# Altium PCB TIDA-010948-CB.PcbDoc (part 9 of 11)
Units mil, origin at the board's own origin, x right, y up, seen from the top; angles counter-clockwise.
Board outline 8100 x 8400 mil, 8 copper layers (L01 - TOP, L02 - GND, L03 - SIG, L04 - GND, L05 - PWR, L06 - SIG, L07 - GND, L08 - BOTTOM), stack 59.656 mil thick; 711 components, 572 nets, 2646 pads, 1325 vias.
Unrouted connection lines stored in the file: 988.
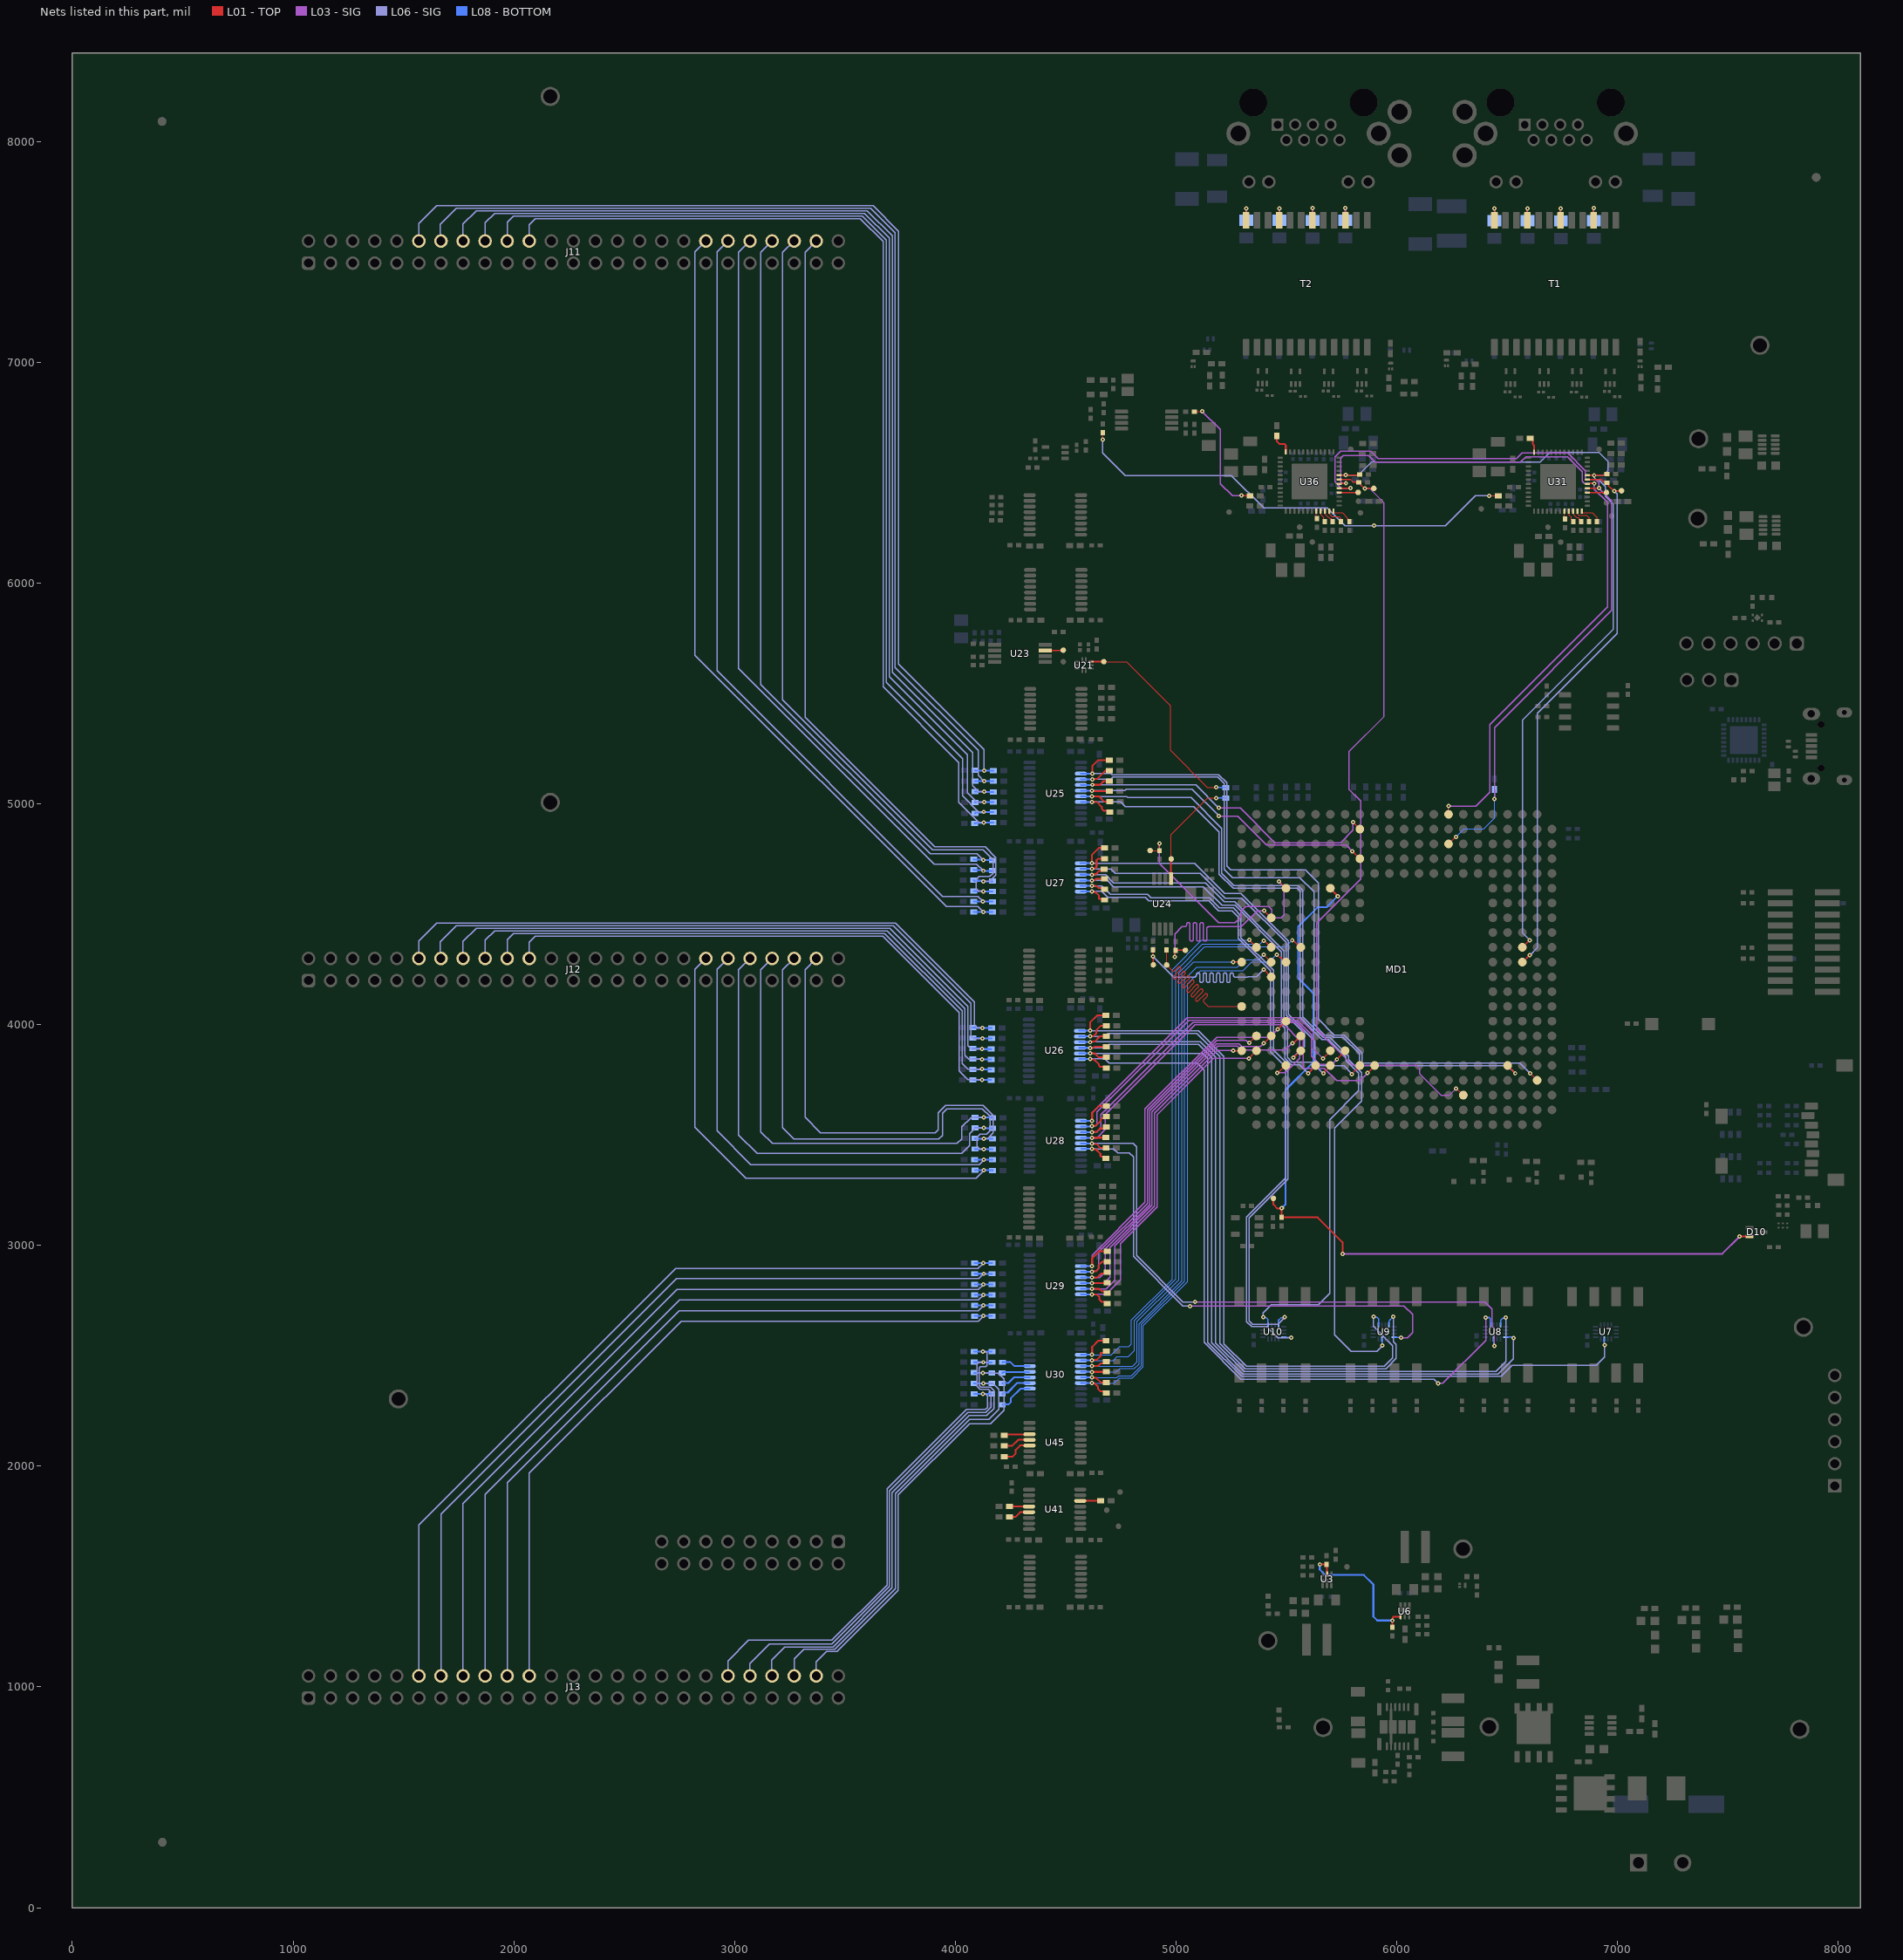
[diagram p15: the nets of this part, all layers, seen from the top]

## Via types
v1: diameter 19.68, hole 7.87, L01 - TOP to L08 - BOTTOM, 1310 vias
v2: diameter 20, hole 7.87, L01 - TOP to L08 - BOTTOM, tented both sides, 7 vias
v3: diameter 200, hole 144, L01 - TOP to L08 - BOTTOM, 6 vias
v4: diameter 20, hole 8, L01 - TOP to L08 - BOTTOM, tented both sides, 2 vias

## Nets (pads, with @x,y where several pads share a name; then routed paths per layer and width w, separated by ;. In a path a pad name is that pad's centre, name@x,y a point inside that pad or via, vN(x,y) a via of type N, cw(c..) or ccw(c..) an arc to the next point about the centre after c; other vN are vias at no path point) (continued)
NetR202_1: R202.1 U30.20 | length 130.9
  L08 - BOTTOM w8: R202.1@4213.62,2470 4214.52,2470.9 4250.02,2470.9 4267.53,2453.39 U30.20@4336.86,2453.39
NetR203_1: R203.1 U30.19 | length 123.6
  L08 - BOTTOM w8: R203.1@4212.68,2422.81 4214.8,2422.81 4217.92,2425.94 U30.19@4335,2425.94
NetR204_1: R204.1 U30.18 | length 134.9
  L08 - BOTTOM w8: R204.1@4213.62,2374 4216.22,2376.59 4240.98,2376.59 4266.59,2402.2 U30.18@4336.86,2402.2
NetR205_1: R205.1 U30.17 | length 144.4
  L08 - BOTTOM w8: R205.1@4213.62,2325.5 4221.43,2333.31 4237.4,2333.31 4280.7,2376.61 U30.17@4336.86,2376.61
NetR206_1: R206.1 U30.16 | length 162.9
  L08 - BOTTOM w8: R206.1@4214.12,2278 4215.62,2279.5 4241,2279.5 4250.5,2289 4250.5,2305.91 4295.61,2351.02 U30.16@4336.86,2351.02
NetR229_1: R229.1 T1.24 | length 110.4
  L01 - TOP w6: T1.24@6442,7642.5 6442.5,7643 v1(6442.5,7697)
  L08 - BOTTOM w6: v1(6442.5,7697) 6442.5,7642 R229.1@6443,7641.5
NetR230_2: R230.2 U31.32 | length 35.6
  L01 - TOP w4.25: U31.32@6759.53,6325.14 6759.53,6293.54 R230.2@6762.36,6290.71
NetR231_1: R231.1 T1.21 | length 109.7
  L01 - TOP w6: T1.21@6592,7642.5 v1(6592,7696.5)
  L08 - BOTTOM w6: v1(6592,7696.5) 6592,7641.5 R231.1@6592.5,7641
NetR233_2: R233.2 U31.33 | length 54.9
  L01 - TOP w4.25: U31.33@6779.21,6325.14 6781.81,6322.54 6781.81,6307.57 6791.26,6298.12 6791.26,6286.15 R233.2@6798.98,6278.43
NetR234_2: R234.2 U31.34 | length 66.6
  L01 - TOP w4.25: U31.34@6798.9,6325.14 6801.5,6322.54 6801.5,6309.89 6814.43,6296.96 6822.41,6296.96 6827.28,6292.08 6827.28,6285.9 R234.2@6835,6278.19
NetR235_1: R235.1 U31.12 | length 71.9
  L01 - TOP w8: R235.1@6603.62,6655 6607.56,6655 6615.37,6647.19 6615.37,6630.02 6621.73,6623.65 U31.12@6621.73,6592.86
NetR237_2: R237.2 U31.35 | length 88.1
  L01 - TOP w4.25: U31.35@6818.58,6325.14 6821.18,6322.54 6821.18,6310.2 6825.18,6306.21 6859.23,6306.21 6871,6294.43 R237.2@6871,6278.69
NetR238_2: R238.2 U31.36 | length 101.4
  L01 - TOP w4.25: U31.36@6838.27,6325.14 6838.27,6320.85 6840.87,6318.25 6868.13,6318.25 6886.28,6318.25 6906.72,6297.81 R238.2@6906.72,6278.69
NetR245_1: R245.1 T1.18 | length 111.6
  L01 - TOP w6: T1.18@6742,7642.5 v1(6742,7697)
  L08 - BOTTOM w6: v1(6742,7697) 6742,7642 R245.1@6743.5,7640.5
NetR248_1: R248.1 T1.15 | length 112.7
  L01 - TOP w6: T1.15@6892,7642.5 v1(6892,7698)
  L08 - BOTTOM w6: v1(6892,7698) 6892,7641.5 R248.1@6892.5,7641
NetR269_1: R269.1 T2.24 | length 108.9
  L01 - TOP w4.5: T2.24@5317,7642.5 T2.24@5318,7643.5
  L01 - TOP w6: T2.24@5318,7643.5 v1(5318,7697)
  L08 - BOTTOM w6: R269.1@5318,7643 v1(5318,7697)
NetR270_2: R270.2 U36.32 | length 35.6
  L01 - TOP w4.25: U36.32@5634.67,6325.61 5634.67,6294.02 R270.2@5637.5,6291.19
NetR271_1: R271.1 T2.21 | length 108.9
  L01 - TOP w6: T2.21@5467,7642.5 5468,7643.5 v1(5468,7697)
  L08 - BOTTOM w6: R271.1@5468,7643 v1(5468,7697)
NetR273_2: R273.2 U36.33 | length 55.7
  L01 - TOP w4.25: U36.33@5654.35,6325.61 5656.95,6323.01 5656.95,6308.05 5668,6297 5668,6282.69 R273.2@5673,6277.69
NetR274_2: R274.2 U36.34 | length 65.7
  L01 - TOP w4.25: U36.34@5674.04,6325.61 5676.64,6323.01 5676.64,6310.36 5688,6299 5690.5,6299 5695.87,6293.63 5699.52,6293.63 5701.78,6291.37 5701.78,6285.9 R274.2@5709.5,6278.19
NetR275_1: R275.1 U36.12 | length 103.2
  L01 - TOP w8: R275.1@5457,6666.38 5457,6640.79 5467.79,6630 5491,6630 5496.87,6624.13 U36.12@5496.87,6593.33
NetR277_2: R277.2 U36.35 | length 88.9
  L01 - TOP w4.25: U36.35@5693.72,6325.61 5696.32,6323.01 5696.32,6310.68 5705.53,6301.47 5738.97,6301.47 5746.5,6293.93 R277.2@5746.5,6278.19
NetR278_2: R278.2 U36.36 | length 99.2
  L01 - TOP w4.25: U36.36@5713.41,6325.61 5713.41,6321.32 5716.01,6318.72 5743.28,6318.72 5753.21,6318.72 5778.22,6293.71 5778.22,6285.05 R278.2@5785.31,6277.96
NetR285_1: R285.1 T2.18 | length 112.3
  L01 - TOP w4.5: T2.18@5617,7642.5 T2.18@5618,7643.5
  L01 - TOP w6: T2.18@5618,7643.5 v1(5618,7698)
  L08 - BOTTOM w8: v1(5618,7698) 5618,7643 R285.1@5619,7642
NetR287_1: R287.1 T2.15 | length 110.9
  L01 - TOP w6: T2.15@5767,7642.5 v1(5767,7698)
  L08 - BOTTOM w8: R287.1@5766,7643 5767,7644 v1(5767,7698)
NetR293_1: R293.1 U41.13 | length 96.7
  L01 - TOP w8: R293.1@4246.12,1770 4271.71,1770 4293.41,1791.7 U41.13@4333.86,1791.7
NetR294_1: R294.1 U41.12 | length 88
  L01 - TOP w8: R294.1@4246.12,1818 4246.48,1817.65 4333.5,1817.65 U41.12@4333.86,1817.29
NetR295_2: R295.2 U41.6 | length 92
  L01 - TOP w8: U41.6@4566.14,1842.88 4566.45,1843.19 4657.57,1843.19 R295.2@4657.88,1843.5
NetR301_1: R301.1 U45.13 | length 145.8
  L01 - TOP w8: R301.1@4221.62,2043.5 4222.62,2042.5 4259,2042.5 4273.5,2057 4273.5,2074 4293.2,2093.7 U45.13@4335.86,2093.7
NetR302_1: R302.1 U45.12 | length 125.7
  L01 - TOP w8: R302.1@4221.62,2091.5 4257,2091.5 4284.8,2119.3 U45.12@4335.86,2119.3
NetR303_1: R303.1 U45.11 | length 116.2
  L01 - TOP w8: R303.1@4222.12,2139 4226.15,2143.03 4334,2143.03 U45.11@4335.86,2144.89
NetTP14_1: TP14.1 U31.40 | length 86.3
  L01 - TOP w5: U31.40@6863.99,6409.66 U31.40@6863.86,6409.79 6863.98,6409.91 TP14.1@6949.74,6409.91 TP14.1@6949.86,6410.03
NetTP19_1: TP19.1 U36.40 | length 86.3
  L01 - TOP w5: U36.40@5739.13,6410.13 U36.40@5739,6410.26 5739.12,6410.38 5824.88,6410.38 TP19.1@5825,6410.5
NetTP24_1: TP24.1 U23.3 | length 82.5
  L01 - TOP w6: U23.3@4407.17,5694.3 4407.93,5695.05 4488.25,5695.05 TP24.1@4489,5695.8
PGOOD_3V3: R13.1 R26.2 U3.2 U6.1 | length 691.2
  L01 - TOP w8: v1(5651,1555) 5651.34,1554.66 5681.66,1554.66 R13.1@5682,1554.32 5683.08,1553.24 5683.08,1512.51 U3.2@5684,1511.59 ; R26.2@5979,1269.69 5979.5,1270.19 5979.5,1300.5 v1(5980,1301) 5981,1302 5981,1313.72 5985.69,1318.41 U6.1@6017.31,1318.41
  L08 - BOTTOM w8: v1(5651,1555) 5651,1532 5676,1507 5851,1507 5894,1464 5894,1318 5911,1301 v1(5980,1301)
PHY1_CLK_IN: R107.2 R246.1 | length 2077.2
  L01 - TOP w4.25: v1(4667.5,6650) R107.2@4667.5,6680.81 ; v1(6419,6395) 6459.88,6395 R246.1@6460.38,6394.5
  L06 - SIG w5.25: v1(4667.5,6650) 4667.5,6589.55 4769.55,6487.5 5249.5,6487.5 5397.24,6339.76 5685.01,6339.76 5764.76,6260 v1(5896.5,6260) 6220,6260 6355.53,6395.53 6418.47,6395.53 v1(6419,6395)
PHY1_RESET: MD1.L20 R243.2 TP32.1 U31.43 | length 2498.7
  L01 - TOP w6: MD1.L20@6568.9,4283.06 6570.48,4283.06 6601.42,4314 v1(6603,4314) ; U31.43@6863.86,6468.84 6926.22,6468.84 6936.07,6459 6945.63,6459 R243.2@6951.5,6453.13 6958.33,6446.3 6958.33,6440.16 6969.2,6429.29 6972.07,6429.29 6984.75,6416.61 v1(6986.03,6416.61) 6986.03,6417.85 TP32.1@7017.88,6417.85
  L06 - SIG w6: v1(6603,4314) 6637,4348 6637,5410 6998.11,5771.11 6998.11,6403.28 6986.03,6415.36 v1(6986.03,6416.61)
PHY2_CLK_IN: R108.2 R286.1 | length 554.5
  L01 - TOP w4.25: R108.2@5083.19,6776 5084.69,6777.5 v1(5118.5,6777.5)
  L01 - TOP w6: v1(5295.5,6396) 5333.38,6396 R286.1@5334.88,6394.5
  L03 - SIG w5.25: v1(5118.5,6777.5) 5201,6695 5201,6450 5255,6396 v1(5295.5,6396)
PHY2_RESET: MD1.Y16 R283.2 TP36.1 U36.43 | length 3673.3
  L01 - TOP w6: U36.43@5739,6469.31 5790.19,6469.31 5802,6457.5 5826.34,6457.5 R283.2@5828.65,6455.19 5829.16,6455.19 5836,6448.35 5836,6445.35 5853.35,6428 v1(5855,6428) 5855.43,6428.43 5895.57,6428.43 TP36.1@5896,6428.86 ; v1(6268.5,3710) 6270.19,3710 6299.49,3680.7 MD1.Y16@6301.18,3680.7
  L03 - SIG w6: v1(5855,6428) 5855.66,6428.66 5876.84,6428.66 5942.05,6363.45 5942.05,5395.55 5782.85,5236.35 5782.85,5066.58 5836.5,5012.93 5836.5,4659 5637.01,4459.51 5637.01,3977.82 5799.88,3814.95 6089.79,3814.95 6103.83,3800.91 6103.83,3776.67 6200.54,3679.96 6238.46,3679.96 v1(6268.5,3710)
PHY_INT: MD1.K20 R242.2 R282.2 U31.44 U36.44 | length 3924.7
  L01 - TOP w6: U36.44@5739,6489 U36.44@5739,6489 5768.94,6488.96 v1(5768.98,6488.93) 5827.89,6488.93 R282.2@5831.09,6492.12 ; MD1.K20@6568.9,4349.99 6569.45,4349.99 6601.95,4382.5 v1(6602.5,4382.5) ; U31.44@6863.86,6488.53 v1(6893.55,6488.53) 6946.3,6488.53 R242.2@6951.97,6494.19
  L06 - SIG w6: v1(5768.98,6488.93) 5826.08,6488.93 5884.66,6547.5 6649.37,6547.5 6692.82,6590.95 6916.18,6590.95 6957.5,6549.63 6957.5,6510 6936.03,6488.53 v1(6893.55,6488.53) 6893.5,6488.47 6893.5,6477.5 6902.16,6468.84 6913.24,6468.84 6945.07,6437.02 6945.07,6393.21 6980.82,6357.45 6980.82,5790.32 6568.81,5378.31 6568.81,4416.19 v1(6602.5,4382.5)
PHY_MDC: MD1.A15 U31.42 U36.42 | length 3342.8
  L01 - TOP w4.25: MD1.A15@6234.25,4952.36 6234.38,4952.48 6234.38,4989.38 v1(6234.5,4989.5)
  L01 - TOP w5: U36.42@5739,6449.63 5739.92,6450.55 5768.58,6450.55 v1(5769.5,6451.47) ; U31.42@6863.86,6449.16 6864.78,6450.08 6893.44,6450.08 v1(6894.36,6451)
  L03 - SIG w5.25: v1(5769.5,6451.47) 5753.33,6451.47 5745.89,6458.91 5745.89,6565.37 5757.2,6576.69 5871.81,6576.69 5901,6547.5 6560.5,6547.5 6584.99,6571.99 6773.37,6571.99 6840.22,6505.14 6840.22,6460.49 6849.71,6451 v1(6894.36,6451) 6894.36,6426.11 6955.25,6365.22 6955.25,5892.75 6421.5,5359 6421.5,5052 6359,4989.5 v1(6234.5,4989.5)
PHY_MDIO: MD1.C15 R236.1 U31.41 U36.41 | length 3666.4
  L01 - TOP w4.25: MD1.C15@6234.25,4818.5 6235.62,4818.5 6267.13,4850 v1(6268.5,4850)
  L01 - TOP w5: U36.41@5739.03,6429.97 v1(5790.5,6430) ; U31.41@6863.86,6429.47 6915.29,6429.5 v1(6915.48,6429.69)
  L03 - SIG w5.25: v1(5790.5,6430) 5748.25,6430 5720.17,6458.07 5720.17,6571.17 5745.89,6596.89 5882.96,6596.89 5916,6563.85 6542.35,6563.85 6567,6588.5 6774.26,6588.5 6854.65,6508.11 6854.65,6473.57 6859.75,6468.47 6901.59,6468.47 6915.48,6454.58 v1(6915.48,6429.69) 6915.48,6429.44 6973.29,6371.64 6973.29,5876.29 6442.5,5345.5 v1(6442.5,5022.5)
  L08 - BOTTOM w4.25: v1(6268.5,4850) 6304.87,4886.37 6393.97,4886.37 6442.5,4934.9 v1(6442.5,5022.5)
  L08 - BOTTOM w5.25: R236.1@6442,5064.88 6442.5,5064.38 v1(6442.5,5022.5)
PORz_OUT: D10.2 MD1.F7 R59.1 TP20.1 | length 4017.1
  L01 - TOP w8: TP20.1@5441,3213 5441,3185 5460,3166 5477,3166 v2(5479,3168) R59.1@5479,3126.69 5641.31,3126.69 5754,3014 v1(5754,2962) ; MD1.F7@5698.82,4617.71 5698.82,4616.45 5732,4583.26 v2(5732,4582) ; v1(7552.5,3040) 7553.16,3040.66 7597.85,3040.66 D10.2@7598.5,3041.31
  L03 - SIG w8: v1(5754,2962) 7474.5,2962 v1(7552.5,3040)
  L08 - BOTTOM w8: v2(5479,3168) 5496,3185 5496,3704.21 5623.01,3831.22 5623.01,4140.67 5553.2,4210.49 5553.2,4444.07 5640.63,4531.5 5681.5,4531.5 v2(5732,4582)
PRG0_IEP1_SYNC0: R128.1 TP30.1 U21.5 | length 965.2
  L01 - TOP w4.25: TP30.1@4672.78,5643.88 4775.62,5643.88 4975,5444.5 4975,5241.5 5142,5074.5 v1(5182.5,5074.5)
  L01 - TOP w8: U21.5@4614.14,5643.88 TP30.1@4672.78,5643.88
  L08 - BOTTOM w6: v1(5182.5,5074.5) 5223.88,5074.5 R128.1@5224.38,5074
PRG0_IEP1_SYNC1: R127.1 TP28.1 U24.1 | length 515.3
  L01 - TOP w4.25: TP28.1@4976.39,4748.62 TP28.1@4978,4750.24 4978,4860 5144,5026 v1(5182.5,5026)
  L01 - TOP w8: U24.1@4976.39,4661.17 TP28.1@4976.39,4748.62
  L08 - BOTTOM w6: v1(5182.5,5026) 5224.38,5026 R127.1@5224.88,5025.5
PRU0_SD0_CLK_SHIFT: MD1.F4 R118.2 TP25.1 | length 1138.3
  L01 - TOP w4.25: TP25.1@4882.5,4788.5 4923.69,4788.5 R118.2@4924.5,4787.69 v1(4924.5,4820.5)
  L01 - TOP w6: v1(5465.5,4647.99) 5466.62,4647.99 5496.91,4617.71 MD1.F4@5498.03,4617.71
  L03 - SIG w5.25: v1(4924.5,4820.5) 4924.5,4729.5 5193,4461 5268.34,4461 5293.78,4486.43 5293.78,4513.54 5314.78,4534.55 5419.96,4534.55 5433,4521.51 5433,4494 5444,4483 5476.23,4483 5489.3,4496.07 5489.3,4624.19 v1(5465.5,4647.99)
PRU0_SD3_CLK_SHIFT: MD1.H3 R119.2 TP26.1 | length 1138
  L01 - TOP w5.25: v1(4995.07,4306.13) 4995.07,4335.19 4997.7,4337.81 5040.69,4337.81 TP26.1@5042,4336.5
  L01 - TOP w6: v1(5399.5,4515.41) MD1.H3@5431.1,4483.85
  L03 - SIG w5.25: v1(4995.07,4306.13) 4995.07,4411.07 5027,4443 5037.24,4443 5039.87,4443 ccw(c5039.87,4450.62) 5047.49,4450.62 5047.49,4454.97 cw(c5055.12,4454.97) 5062.74,4454.97 5062.74,4385.39 ccw(c5070.37,4385.39) 5077.99,4385.39 5077.99,4454.97 cw(c5085.62,4454.97) 5093.24,4454.97 5093.24,4385.39 ccw(c5100.87,4385.39) 5108.49,4385.39 5108.49,4454.97 cw(c5116.12,4454.97) 5123.74,4454.97 5123.74,4385.39 ccw(c5131.37,4385.39) 5138.99,4385.39 5138.99,4435.38 cw(c5146.62,4435.38) 5146.62,4443 5162.5,4443 5295.09,4443 5367.5,4515.41 v1(5399.5,4515.41)
PRU1_SD0_CLK_SHIFT: MD1.M3 R120.2 TP27.1 | length 1061.9
  L01 - TOP w4.25: v1(4896,4308.5) R120.2@4896,4337.81
  L01 - TOP w6: R120.2@4895,4338.81 R120.2@4896,4337.81 ; v1(4896,4308.5) 4896.5,4308 4896.5,4271 TP27.1@4897,4270.5 ; v1(5398,4249.5) 5398,4249.37 5431.1,4216.27 MD1.M3@5431.1,4216.14
  L06 - SIG w5.25: v1(4896,4308.5) 4989.5,4215 5082,4215 5084.63,4215 ccw(c5084.63,4222.62) 5092.25,4222.62 5092.25,4226.21 cw(c5099.88,4226.21) 5107.5,4226.21 5107.5,4198.31 ccw(c5115.13,4198.31) 5122.75,4198.31 5122.75,4226.21 cw(c5130.38,4226.21) 5138,4226.21 5138,4198.31 ccw(c5145.63,4198.31) 5153.25,4198.31 5153.25,4226.21 cw(c5160.88,4226.21) 5168.5,4226.21 5168.5,4198.31 ccw(c5176.13,4198.31) 5183.75,4198.31 5183.75,4226.21 cw(c5191.38,4226.21) 5199,4226.21 5199,4198.31 ccw(c5206.63,4198.31) 5214.25,4198.31 5214.25,4226.21 cw(c5221.88,4226.21) 5229.5,4226.21 5229.5,4198.31 ccw(c5237.13,4198.31) 5244.75,4198.31 5244.75,4226.21 cw(c5252.38,4226.21) 5260,4226.21 5260,4222.62 ccw(c5267.63,4222.62) 5267.63,4215 5284.86,4215 5324.18,4215 5326.12,4216.94 5365.44,4216.94 v1(5398,4249.5)
PRU1_SD3_CLK_SHIFT: MD1.P1 R121.2 TP29.1 | length 1159.5
  L01 - TOP w4.25: R121.2@4957.5,4337.81 TP29.1@4957.5,4270 4982.36,4245.14 4983.87,4243.63 ccw(c4988.91,4248.67) 4993.94,4243.63 5009.72,4259.41 cw(c5014.76,4254.37) 5019.79,4259.41 cw(c5014.76,4254.37) 5019.79,4249.33 4989.4,4218.94 ccw(c4994.44,4213.9) 4989.4,4208.86 ccw(c4994.44,4213.9) 4999.48,4208.86 5029.87,4239.25 cw(c5034.91,4234.22) 5039.95,4239.25 cw(c5034.91,4234.22) 5039.95,4229.18 5009.56,4198.79 ccw(c5014.6,4193.75) 5009.56,4188.71 ccw(c5014.6,4193.75) 5019.63,4188.71 5050.02,4219.1 cw(c5055.06,4214.06) 5060.1,4219.1 cw(c5055.06,4214.06) 5060.1,4209.02 5029.71,4178.64 ccw(c5034.75,4173.6) 5029.71,4168.56 ccw(c5034.75,4173.6) 5039.79,4168.56 5070.18,4198.95 cw(c5075.21,4193.91) 5080.25,4198.95 cw(c5075.21,4193.91) 5080.25,4188.87 5049.86,4158.48 ccw(c5054.9,4153.44) 5049.86,4148.41 ccw(c5054.9,4153.44) 5059.94,4148.41 5090.33,4178.8 cw(c5095.37,4173.76) 5100.4,4178.8 cw(c5095.37,4173.76) 5100.4,4168.72 5070.02,4138.33 ccw(c5075.05,4133.29) 5070.01,4128.25 ccw(c5075.05,4133.29) 5080.09,4128.25 5110.48,4158.64 cw(c5115.52,4153.61) 5120.56,4158.64 cw(c5115.52,4153.61) 5120.56,4148.57 5090.17,4118.18 ccw(c5095.21,4113.14) 5090.17,4108.1 ccw(c5095.21,4113.14) 5100.24,4108.1 5130.63,4138.49 cw(c5135.67,4133.45) 5140.71,4138.49 cw(c5135.67,4133.45) 5140.71,4128.41 5124.94,4112.64 ccw(c5129.97,4107.6) 5124.94,4102.56 5139.26,4088.24 5145.22,4082.28 MD1.P1@5297.24,4082.28
PWM_A1_H: MD1.W21 R145.1 U25.3 | length 3373.5
  L01 - TOP w6: v1@6604,3779.73 MD1.W21@6635.83,3747.9
  L01 - TOP w8: v1(4620,5137) 4620,5171.29 4646.02,5197.31 R145.1@4698.25,5197.31 ; v1@6604,3779.73 v1(6604,3780) ; MD1.W21@6635.83,3747.63 MD1.W21@6635.83,3747.9
  L06 - SIG w5.25: v1(4620,5137) 4705.34,5137 4710.3,5132.03 5193,5132.03 5229.38,5095.65 5229.38,4718.12 5247.1,4700.4 5584.82,4700.4 5644.2,4641.02 5644.2,4024.29 5715.6,3952.89 5761.28,3952.89 5843.17,3870.99 5843.17,3828.18 5846.04,3825.31 6558.69,3825.31 v1(6604,3780)
  L08 - BOTTOM w8: U25.3@4569.14,5136.57 4569.36,5136.78 4619.78,5136.78 v1(4620,5137)
PWM_A1_L: MD1.V19 R146.1 U25.4 | length 3274.7
  L01 - TOP w6: MD1.V19@6501.97,3814.05 v1@6536,3780.01
  L01 - TOP w8: v1(4620,5111.5) 4620.84,5112.34 4641.84,5112.34 4679.31,5149.81 R146.1@4697.75,5149.81 ; MD1.V19@6501.97,3814.05 MD1.V19@6501.97,3814.56 ; v1(6536,3779.5) v1@6536,3780.01
  L06 - SIG w5.25: v1(4620,5111.5) 4704.97,5111.5 4715.25,5121.78 5188.72,5121.78 5218.5,5092 5218.5,4702.5 5255.54,4665.46 5560.34,4665.46 5624.42,4601.37 5624.42,4001.07 5672.43,3953.07 5700.92,3953.07 5711.35,3942.64 5756.5,3942.64 5830.77,3868.37 5830.77,3826.08 5842.64,3814.21 6501.29,3814.21 v1(6536,3779.5)
  L08 - BOTTOM w8: U25.4@4569.14,5110.98 4569.4,5111.24 4619.74,5111.24 v1(4620,5111.5)
PWM_A2_H: MD1.V9 R173.1 U27.3 | length 2033.9
  L01 - TOP w6: v1(5795.65,3776.15) 5795.65,3776.84 5832.68,3813.87 MD1.V9@5832.68,3814.56
  L01 - TOP w8: v1(4618.56,4730.94) 4618.56,4768.77 4649.79,4800 R173.1@4675.38,4800
  L06 - SIG w5.25: v1(4618.56,4730.94) 5083.56,4730.94 5220.36,4594.14 5293.01,4594.14 5508.72,4378.43 5508.72,4046.77 5630.08,3925.4 5630.08,3834.16 5650.62,3813.63 5760.87,3813.63 5795.65,3778.85 v1(5795.65,3776.15)
  L08 - BOTTOM w8: U27.3@4567.96,4730.68 4618.3,4730.68 v1(4618.56,4730.94)
PWM_A2_L: MD1.U5 R174.1 U27.4 | length 1785.7
  L01 - TOP w6: v1(5531,3851) 5532.74,3851 5563.23,3881.49 MD1.U5@5564.96,3881.49
  L01 - TOP w8: v1(4618.56,4705.44) 4620.79,4707.68 4633.18,4707.68 4639.5,4714 4639.5,4744.5 4647,4752 R174.1@4675.38,4752
  L06 - SIG w5.25: v1(4618.56,4705.44) 4704.51,4705.44 4724.95,4685 5110.5,4685 5222.5,4573 5298.34,4573 5498.47,4372.87 5498.47,4042.52 5581,3959.99 5581,3901 v1(5531,3851)
  L08 - BOTTOM w8: U27.4@4568.01,4705.14 4618.25,4705.14 v1(4618.56,4705.44)
PWM_A3_H: R151.1 U9.1 U26.3 | length 3229.4
  L01 - TOP w8: v1(4611.56,3972.44) 4611.56,4010.56 4643,4042 R151.1@4682.88,4042
  L06 - SIG w5.25: v1(4611.56,3972.44) 4613,3971 5101.46,3971 5216.29,3856.18 5216.29,2554.27 5318.56,2452 5942.57,2452 5981,2490.43 5981,2546.5 5894,2633.5 v1(5894,2676)
  L08 - BOTTOM w6: v1(5894,2676) 5896.62,2673.38 5911.32,2673.38 5912.97,2671.73 5913.14,2671.73 5917.38,2667.49 U9.1@5917.38,2637.53
  L08 - BOTTOM w8: U26.3@4560.96,3972.18 4611.3,3972.18 v1(4611.56,3972.44)
PWM_A3_L: R152.1 U9.4 U26.4 | length 3193
  L01 - TOP w8: v1(4611.23,3947.27) 4611.56,3946.94 4612,3946.5 4624.47,3946.5 4638.97,3961 4638.97,3975.19 4657.79,3994 R152.1@4683.38,3994
  L06 - SIG w5.25: v1(4611.23,3947.27) 4611.5,3947 4677.79,3947 4690.79,3960 5093.45,3960 5198.75,3854.7 5198.75,2556.25 5314,2441 5951,2441 5997.5,2487.5 5997.5,2551.5 5984.69,2564.32 v1(5984.69,2677)
  L08 - BOTTOM w6: U9.4@5964.62,2639.5 5964.62,2657.62 5970,2663 5970,2663.3 5983.7,2677 v1(5984.69,2677)
  L08 - BOTTOM w8: U26.4@4561.02,3946.62 4610.59,3946.62 v1(4611.23,3947.27)
PWM_A4_H: MD1.U7 R179.1 U28.3 | length 1593.3
  L01 - TOP w6: v1(5665.5,3846) 5665.5,3847.09 5698.82,3880.4 MD1.U7@5698.82,3881.49
  L01 - TOP w8: v1(4619.74,3564.83) 4619.74,3600.93 4649.19,3630.38 R179.1@4683.38,3630.38
  L03 - SIG w5.25: v1(4619.74,3564.83) 4619.74,3600.93 5050.31,4031.5 5555.66,4031.5
  L03 - SIG w6: 5555.66,4031.5 5623.73,3963.43 5623.73,3887.77 v1(5665.5,3846)
  L08 - BOTTOM w8: U28.3@4569.14,3564.57 4619.48,3564.57 v1(4619.74,3564.83)
PWM_A4_L: MD1.U8 R180.1 U28.4 | length 1681.1
  L01 - TOP w6: v1(5728.04,3841.54) 5728.04,3842.66 5765.75,3880.37 MD1.U8@5765.75,3881.49
  L01 - TOP w8: v1(4619.74,3539.33) 4621.91,3541.5 4635,3541.5 4658.75,3565.25 4658.75,3570.46 4663.43,3575.14 4675.31,3575.14 R180.1@4683.13,3582.96
  L03 - SIG w5.25: v1(4619.74,3539.33) 4622.19,3541.79 4635.29,3541.79 4641.5,3548 4641.5,3604 5057.6,4020.1 5547.89,4020.1 5613.11,3954.88 5613.11,3856.9 5651.09,3818.92 5705.42,3818.92 v1(5728.04,3841.54)
  L08 - BOTTOM w8: U28.4@4569.19,3539.02 4619.43,3539.02 v1(4619.74,3539.33)
PWM_A5_H: MD1.R4 R193.1 U29.3 | length 1782.2
  L01 - TOP w6: v1(5461,3979.5) 5461.59,3979.5 5497.44,4015.35 MD1.R4@5498.03,4015.35
  L01 - TOP w8: v1(4619.74,2906.33) 4619.74,2941.74 4651,2973 R193.1@4688.38,2973
  L03 - SIG w5.25: v1(4619.74,2906.33) 4619.27,2906.8 4619.27,2954.26 4859.5,3194.5 4859.5,3618.09 5183.93,3942.52 5424.02,3942.52 v1(5461,3979.5)
  L08 - BOTTOM w8: U29.3@4569.14,2906.07 4619.48,2906.07 v1(4619.74,2906.33)
PWM_A5_L: MD1.T2 R194.1 U29.4 | length 1635.1
  L01 - TOP w6: v1(5331,3917.5) 5332.13,3917.5 5363.05,3948.42 MD1.T2@5364.17,3948.42
  L01 - TOP w8: v1(4619.74,2880.83) 4621.41,2882.5 4637,2882.5 4649,2894.5 4649,2910.29 4664.21,2925.5 R194.1@4688.38,2925.5
  L03 - SIG w5.25: v1(4619.74,2880.83) 4621.87,2882.96 4637.46,2882.96 4649,2894.5 4649,2969.5 4869.75,3190.25 4869.75,3613.84 5184.65,3928.74 5317.18,3928.74 5328.42,3917.5 v1(5331,3917.5)
  L08 - BOTTOM w8: U29.4@4569.19,2880.52 4619.43,2880.52 v1(4619.74,2880.83)
PWM_A6_H: MD1.K2 R207.1 U30.3 | length 2582
  L01 - TOP w6: v1(5331.5,4383) 5331.5,4382.83 5364.17,4350.16 MD1.K2@5364.17,4349.99
  L01 - TOP w8: v1(4619.74,2504.84) 4619.74,2539.76 4648.12,2568.14 R207.1@4682.98,2568.14
  L03 - SIG w5.25: v1@5330.5,4382 v1(5331.5,4383)
  L08 - BOTTOM w4.25: v1(4619.74,2504.84) 4707.18,2504.84 4743.77,2541.43 4785.93,2541.43 4798,2553.5 4798,2662 4982.36,2846.36 4982.36,4248.86 5115.5,4382 v1@5330.5,4382
  L08 - BOTTOM w8: U30.3@4569.14,2504.57 4619.48,2504.58 v1(4619.74,2504.84)
PWM_A6_L: MD1.K3 R208.1 U30.4 | length 2648.9
  L01 - TOP w6: v1(5397,4380.5) 5398.8,4380.5 5429.3,4349.99 MD1.K3@5431.1,4349.99
  L01 - TOP w8: v1(4619.74,2479.34) 4621.97,2481.58 4641.58,2481.58 4658.06,2498.06 4658.06,2510.99 4660.19,2513.12 4675.84,2513.12 R208.1@4683.65,2520.93
  L08 - BOTTOM w4.25: v1(4619.74,2479.34) 4716.1,2479.34 4732.26,2495.5 4784.5,2495.5 4812,2523 4812,2660.5 4998.44,2846.94 4998.44,4242.44 5120.5,4364.5 5381,4364.5 v1(5397,4380.5)
  L08 - BOTTOM w8: U30.4@4569.19,2479.03 4619.43,2479.03 v1(4619.74,2479.34)
PWM_B1_H: MD1.B9 R147.1 U25.5 | length 1529.3
  L01 - TOP w6: v1@5802,4916.3 MD1.B9@5832.68,4885.62
  L01 - TOP w8: v1(4620,5086) 4655.35,5086 4672.16,5102.81 R147.1@4697.75,5102.81 ; v1@5802,4916.3 v1(5802,4916.5) ; MD1.B9@5832.68,4885.43 MD1.B9@5832.68,4885.62
  L03 - SIG w5.25: v1(5193.5,4981.5) 5291,4981.5 5448.33,4824.17 5745.55,4824.17 5802,4880.62 v1(5802,4916.5)
  L06 - SIG w5.25: v1(4620,5086) 5089,5086 v1(5193.5,4981.5)
  L08 - BOTTOM w8: U25.5@4569.14,5085.39 4569.45,5085.69 4619.69,5085.69 v1(4620,5086)
PWM_B1_L: MD1.D9 R148.1 U25.6 | length 1476.2
  L01 - TOP w6: v1@5799.62,4784 MD1.D9@5832.05,4751.57
  L01 - TOP w8: v1(4619.5,5059.5) 4620.84,5058.16 4696.91,5058.16 R148.1@4698.25,5056.81 ; v1(5799,4784) v1@5799.62,4784 ; MD1.D9@5832.05,4751.57 MD1.D9@5832.68,4751.57
  L03 - SIG w5.25: v1(5194.25,4944.25) 5278.84,4944.25 5410.59,4812.5 5770.5,4812.5 v1(5799,4784)
  L06 - SIG w5.25: v1(4619.5,5059.5) 4767.85,5059.5 4774.31,5065.97 5073.03,5065.97 v1@5194.25,4944.75
  L08 - BOTTOM w8: U25.6@4569.14,5059.8 4569.29,5059.65 4619.35,5059.65 v1(4619.5,5059.5)
PWM_B2_H: MD1.V7 R175.1 U27.5 | length 1864.8
  L01 - TOP w6: v1(5667,3779) 5667,3780.87 5698.82,3812.69 MD1.V7@5698.82,3814.56
  L01 - TOP w8: v1@4615.84,4676.72 v1(4618.06,4678.94) 4620.11,4681 4636.52,4681 4652.21,4696.69 4667.07,4696.69 R175.1@4674.88,4704.5
  L06 - SIG w5.25: v1(4618.06,4678.94) 4680.19,4678.94 4717.15,4641.99 5133.01,4641.99 5218,4557 5264.94,4557 5488.22,4333.72 5488.22,4006.28 5504.63,3989.87 5504.63,3850.37 5525.5,3829.5 5616.5,3829.5 v1(5667,3779)
  L08 - BOTTOM w8: U27.5@4567.85,4679.09 4617.91,4679.09 v1(4618.06,4678.94)
PWM_B2_L: MD1.V6 R176.1 U27.6 | length 1777.8
  L01 - TOP w6: v1(5599.5,3779) 5599.5,3780.59 5631.89,3812.98 MD1.V6@5631.89,3814.56
  L01 - TOP w8: v1@4616.87,4651.76 v1(4618.06,4652.94) 4618.61,4653.5 4631.5,4653.5 4637.5,4659.5 R176.1@4675.38,4659.5
  L06 - SIG w5.25: v1(4618.06,4652.94) 4688.01,4652.94 4716.49,4624.47 5123.53,4624.47 5207.5,4540.5 5266.94,4540.5 5477.97,4329.47 5477.97,3998.97 5492.7,3984.24 5492.7,3847.8 5522.5,3818 5560.5,3818 v1(5599.5,3779)
  L08 - BOTTOM w8: U27.6@4568.05,4653.3 4617.7,4653.3 v1(4618.06,4652.94)
PWM_B3_H: R153.1 U8.4 U26.5 | length 3664.1
  L01 - TOP w8: v1@4610.09,3919.47 v1(4611.06,3920.44) 4613.29,3922.68 4631.31,3922.68 4655.63,3947 R153.1@4683.38,3947
  L06 - SIG w5.25: v1(4611.06,3920.44) 4613.61,3923 5109.92,3923 5179.5,3853.42 5179.5,2558 5309,2428.5 6448.11,2428.5 6494,2474.39 v1(6494,2673)
  L08 - BOTTOM w6: U8.4@6470.62,2639.5 6470.62,2660.62 6480.38,2670.38 6491.38,2670.38 v1(6494,2673)
  L08 - BOTTOM w8: U26.5@4560.85,3920.59 4610.91,3920.59 v1(4611.06,3920.44)
PWM_B3_L: R154.1 U8.8 U26.6 | length 3586.3
  L01 - TOP w8: v1@4609.26,3892.65 v1(4611.06,3894.44) 4611.5,3894 4625.5,3894 4631,3899.5 R154.1@4683.38,3899.5
  L06 - SIG w5.25: v1(4611.06,3894.44) 4680.88,3894.44 4696.93,3910.5 5101.48,3910.5 5160.5,3851.48 5160.5,2558.5 5301.5,2417.5 6459.27,2417.5 6529,2487.23 v1(6529,2580.32)
  L08 - BOTTOM w6: U8.8@6494.24,2584.38 6521.23,2584.38 6525.3,2580.32 v1(6529,2580.32)
  L08 - BOTTOM w8: U26.6@4561.05,3894.8 4610.7,3894.8 v1(4611.06,3894.44)
PWM_B4_H: MD1.V10 R181.1 U28.5 | length 1886.8
  L01 - TOP w6: v1(5868,3780.5) 5868,3781.73 5899.61,3813.33 MD1.V10@5899.61,3814.56
  L01 - TOP w8: v1(4619.24,3512.83) 4621.47,3515.06 4641.06,3515.06 4655.38,3529.38 4675.97,3529.38 R181.1@4683.13,3536.53
  L03 - SIG w5.25: v1(4619.24,3512.83) 4642.2,3512.83 4658.75,3529.38 4658.75,3592 5076.6,4009.85 5543.35,4009.85 5575.87,3977.34 5575.87,3805.71 5578.94,3802.63 5671,3802.63 5727.93,3745.71 5833.21,3745.71 v1(5868,3780.5)
  L08 - BOTTOM w8: U28.5@4569.03,3512.98 4619.09,3512.98 v1(4619.24,3512.83)
PWM_B4_L: MD1.V4 R182.1 U28.6 | length 1602
  L01 - TOP w6: v1(5458,3781.5) 5461.49,3781.5 5494.55,3814.56 MD1.V4@5498.03,3814.56
  L01 - TOP w8: v1(4619.24,3486.83) 4620.26,3487.85 4681.49,3487.85 R182.1@4682.52,3488.88
  L03 - SIG w5.25: v1(4619.24,3486.83) 4641.48,3486.83 4679.55,3524.9 4679.55,3592.55 5086.39,3999.39 5490.12,3999.39 5560.87,3928.64 5560.87,3847.83 5494.55,3781.5 v1(5458,3781.5)
  L08 - BOTTOM w8: U28.6@4569.23,3487.18 4618.89,3487.18 v1(4619.24,3486.83)
PWM_B5_H: MD1.T3 R195.1 U29.5 | length 1714.9
  L01 - TOP w6: v1(5398,3915.5) 5398.09,3915.5 5431.01,3948.42 MD1.T3@5431.1,3948.42
  L01 - TOP w8: v1(4619.24,2854.33) 4642.33,2854.33 4660.63,2872.63 4683.01,2872.63 R195.1@4688.38,2878
  L03 - SIG w5.25: v1(4619.24,2854.33) 4653.83,2854.33 4678.76,2879.26 4678.76,2983.26 4880,3184.5 4880,3609.5 5183.5,3913 5284.9,3913 5297.87,3900.03 5382.53,3900.03 v1(5398,3915.5)
  L08 - BOTTOM w8: U29.5@4569.03,2854.48 4619.09,2854.48 v1(4619.24,2854.33)
PWM_B5_L: MD1.T5 R196.1 U29.6 | length 1872.5
  L01 - TOP w6: v1(5527,3916) 5529.62,3918.62 5534.64,3918.62 5564.44,3948.42 MD1.T5@5564.96,3948.42
  L01 - TOP w8: v1(4619.24,2828.33) 4620.32,2829.41 4687.29,2829.41 R196.1@4688.38,2830.5
  L03 - SIG w5.25: v1(4619.24,2828.33) 4672.52,2828.33 4700.54,2856.35 4700.54,2990.54 4891,3181 4891,3605.25 5188.5,3902.75 5276.75,3902.75 5295.5,3884 5495,3884 v1(5527,3916)
  L08 - BOTTOM w8: U29.6@4569.23,2828.68 4618.89,2828.68 v1(4619.24,2828.33)
PWM_B6_H: MD1.K5 R209.1 U30.5 | length 2803.6
  L01 - TOP w6: v1(5526.5,4382.5) 5529.48,4382.5 5561.98,4349.99 MD1.K5@5564.96,4349.99
  L01 - TOP w8: v1(4619.24,2452.84) 4646.23,2452.84 4659.81,2466.43 4675.42,2466.43 R209.1@4683.23,2474.24
  L08 - BOTTOM w4.25: v1(4619.24,2452.84) 4803.84,2452.84 4823,2472 4823,2655.5 5012,2844.5 5012,4235 5129.21,4352.21 5496.21,4352.21 v1(5526.5,4382.5)
  L08 - BOTTOM w8: U30.5@4569.03,2452.99 4619.09,2452.99 v1(4619.24,2452.84)
PWM_B6_L: MD1.L1 R210.1 U30.6 | length 2484.1
  L01 - TOP w6: v1(5259,4283.5) 5259.22,4283.28 5297.03,4283.28 MD1.L1@5297.24,4283.06
  L01 - TOP w8: v1(4619.24,2426.84) 4619.38,2426.99 4683.71,2426.99 R210.1@4683.86,2427.13
  L08 - BOTTOM w4.25: v1(4619.24,2426.84) 4619.85,2426.23 4729.02,2426.23 4745.92,2443.13 4812.13,2443.13 4832.5,2463.5 4832.5,2645 5027,2839.5 5027,4231 5079.5,4283.5 v1(5259,4283.5)
  L08 - BOTTOM w8: U30.6@4569.23,2427.19 4618.89,2427.19 v1(4619.24,2426.84)
PWM_C1_H: R149.1 U9.11 U25.7 | length 3872.7
  L01 - TOP w8: v1(4619.5,5033.5) 4650.68,5033.5 4674.87,5009.31 R149.1@4699.25,5009.31
  L06 - SIG w5.25: v1(4619.5,5033.5) 4776.3,5033.5 4781.55,5028.25 5067.75,5028.25 5207,4889 5207,4685.5 5262.5,4630 5552.59,4630 5573.85,4608.73 5573.85,4287.15 5574,4287 5574,4034.77 5665.95,3942.82 5695.67,3942.82 5780.77,3857.72 5780.77,3842.5 5781.57,3841.69 5781.57,3840.62 5840.52,3781.67 5840.52,3654.02 5718,3531.5 5718,2594.5 5792.5,2520 5909,2520 v1(5935,2546)
  L08 - BOTTOM w6: U9.11@5933.13,2576.5 5934.06,2575.57 5934.06,2546.94 v1(5935,2546)
  L08 - BOTTOM w8: U25.7@4569.14,5034.2 4569.49,5033.85 4619.15,5033.85 v1(4619.5,5033.5)
PWM_C1_L: R150.1 U10.1 U25.8 | length 3791.9
  L01 - TOP w8: v1(4619.5,5008.5) 4641.5,5008.5 4664,4986 4664,4977 4672,4969 4692.57,4969 R150.1@4699.75,4961.81
  L06 - SIG w5.25: v1(4619.5,5008.5) 4749.62,5008.5 4770.41,4987.71 5080.29,4987.71 5195,4873 5195,4681.5 5259,4617.5 5550,4617.5 5561.97,4605.53 5561.97,4032.3 5661.71,3932.57 5690.7,3932.57 5769.65,3853.62 5769.65,3838.04 5827.5,3780.19 5827.5,3700.32 5696,3568.82 5696,2782 5645.78,2731.78 5432.08,2731.78 5395,2694.7 v1(5395,2674)
  L08 - BOTTOM w6: v1(5395,2674) 5397.62,2671.38 5409.48,2671.38 5416.38,2664.49 U10.1@5416.38,2637.53
  L08 - BOTTOM w8: U25.8@4569.14,5008.61 4569.2,5008.56 4619.44,5008.56 v1(4619.5,5008.5)
PWM_C2_H: R177.1 U10.4 U27.7 | length 3078
  L01 - TOP w8: v1@4618,4628 v1(4618.06,4627.94) 4639.06,4627.94 4647.63,4619.37 4668.01,4619.37 R177.1@4675.38,4612
  L06 - SIG w5.25: v1(4618.06,4627.94) 4663.94,4627.94 4702.35,4589.53 4871.08,4589.53 4886.62,4574 5151.5,4574 5196,4529.5 5259,4529.5 5294.35,4494.15 5294.35,4392.55 5441.07,4245.83 5441.07,3884.94 5506.73,3819.27 5506.73,3300.73 5330.5,3124.5 5330.5,2659 5346.5,2643 5461,2643 v1(5492,2674)
  L08 - BOTTOM w6: U10.4@5463.62,2639.5 5463.62,2660.31 5474.7,2671.38 5489.38,2671.38 v1(5492,2674)
  L08 - BOTTOM w8: U27.7@4567.76,4628 4618,4628 v1(4618.06,4627.94)
PWM_C2_L: R178.1 U10.8 U27.8 | length 3107.1
  L01 - TOP w8: v1@4615.76,4600.76 v1(4618,4603) 4620.24,4600.76 4634.74,4600.76 4649.79,4585.71 4649.79,4582.82 4651,4581.6 4651,4569.19 4670.69,4569.19 R178.1@4675.38,4564.5
  L06 - SIG w5.25: v1(4618,4603) 4664.09,4603 4690.12,4576.97 4859.95,4576.97 4876.98,4559.94 5149.06,4559.94 5193,4516 5253,4516 5281.68,4487.32 5281.68,4390.73 5427.09,4245.32 5427.09,4235.54 5427.18,4235.45 5427.18,3877.57 5496.11,3808.65 5496.11,3305.13 5319.88,3128.9 5319.88,2654.6 5342.1,2632.38 5409.95,2632.38 5461.04,2581.28 v1(5521,2581.28)
  L08 - BOTTOM w6: U10.8@5487.24,2584.38 5488.18,2583.44 5518.84,2583.44 v1(5521,2581.28)
  L08 - BOTTOM w8: U27.8@4569.14,4602.7 4569.29,4602.85 4617.85,4602.85 v1(4618,4603)
PWM_C3_H: R155.1 U7.11 U26.7 | length 3939.2
  L01 - TOP w8: v1@4611,3869.5 v1(4611.06,3869.44) 4632.56,3869.44 4650,3852 R155.1@4683.38,3852
  L06 - SIG w5.25: v1(4611.06,3869.44) 5121.56,3869.44 5143.5,3847.5 5143.5,2559.94 5296.94,2406.5 6473,2406.5 6523,2456.5 6902.64,2456.5 6941,2494.86 v1(6941,2549)
  L08 - BOTTOM w6: U7.11@6939.13,2576.5 6939,2576.38 6939,2551 v1(6941,2549)
  L08 - BOTTOM w8: U26.7@4560.76,3869.5 4611,3869.5 v1(4611.06,3869.44)
PWM_C3_L: R156.1 U8.1 U26.8 | length 3503.2
  L01 - TOP w8: v1(4611,3844.5) 4613.24,3842.26 4628.74,3842.26 4649.5,3821.5 4649.5,3815 4655.63,3808.87 4678.01,3808.87 R156.1@4683.38,3803.5
  L03 - SIG w5.25: v1(6187,2375) 6209,2375 6403,2569 v1(6403,2673)
  L06 - SIG w5.25: v1(4611,3844.5) 4677.99,3844.5 4697.33,3825.15 5096.85,3825.15 5127.5,3794.5 5127.5,2560.39 5293.89,2394 6168,2394 v1(6187,2375)
  L08 - BOTTOM w6: v1(6403,2673) 6419,2673 6423.38,2668.62 U8.1@6423.38,2637.53
  L08 - BOTTOM w8: U26.8@4562.29,3844.35 4610.85,3844.35 v1(4611,3844.5)
PWM_C4_H: R183.1 U8.11 U28.7 | length 2736.2
  L01 - TOP w8: v1(4619.24,3461.83) 4621.47,3459.59 4638.91,3459.59 4657.36,3441.14 R183.1@4682.98,3441.14
  L03 - SIG w5.25: v1(5086,2743.5) 5087.12,2742.38 6399.69,2742.38 6430.84,2711.23 6430.84,2632.16 6441.22,2621.78 v1(6441.22,2545)
  L06 - SIG w5.25: v1(4619.24,3461.83) 4805.1,3461.83 4820.5,3446.42 4820.5,2954.5 5031.5,2743.5 v1(5086,2743.5)
  L08 - BOTTOM w6: U8.11@6439.13,2576.5 6440.06,2575.57 6440.06,2546.16 v1(6441.22,2545)
  L08 - BOTTOM w8: U28.7@4568.94,3461.89 4619.18,3461.89 v1(4619.24,3461.83)
PWM_C4_L: R184.1 U9.8 U28.8 | length 2336
  L01 - TOP w8: v1(4619.18,3436.89) 4620.57,3435.5 4636.5,3435.5 4657.29,3414.71 4657.29,3406.47 4661.97,3401.79 4675.09,3401.79 R184.1@4682.88,3394
  L03 - SIG w5.25: v1(5062.5,2725) 6032.95,2725 6071,2686.95 6071,2605.5 6047.5,2582 v1(6020,2582)
  L06 - SIG w5.25: v1(4619.18,3436.89) 4717.4,3436.89 4736.28,3418 4788.5,3418 4806.5,3400 4806.5,2950.09 5031.59,2725 v1(5062.5,2725)
  L08 - BOTTOM w6: U9.8@5988.24,2584.38 5989.18,2583.44 6018.56,2583.44 v1(6020,2582)
  L08 - BOTTOM w8: U28.8@4570.47,3436.74 4619.03,3436.74 v1(4619.18,3436.89)
PWM_C5_H: MD1.U1 R197.1 U29.7 | length 1590
  L01 - TOP w6: v1(5258.5,3882) 5258.76,3881.74 5296.99,3881.74 MD1.U1@5297.24,3881.49
  L01 - TOP w8: v1(4619.24,2803.33) 4652.15,2803.33 4664.66,2790.81 4680.57,2790.81 R197.1@4688.38,2783
  L03 - SIG w5.25: v1(4619.24,2803.33) 4682.84,2803.33 4721.82,2842.31 4721.82,2997.33 4902.12,3177.63 4902.12,3598.12 5186,3882 v1(5258.5,3882)
  L08 - BOTTOM w8: U29.7@4568.94,2803.39 4619.18,2803.39 v1(4619.24,2803.33)
PWM_C5_L: MD1.U2 R198.1 U29.8 | length 1686.3
  L01 - TOP w6: v1(5329.5,3847) 5329.59,3847 5364.08,3881.49 MD1.U2@5364.17,3881.49
  L01 - TOP w8: v1(4619.18,2778.39) 4640.11,2778.39 4651.45,2767.05 4651.45,2756 4664.14,2743.31 4680.57,2743.31 R198.1@4688.38,2735.5
  L03 - SIG w5.25: v1(4619.18,2778.39) 4682.33,2778.39 4748.5,2844.55 4748.5,3008.5 4914,3174 4914,3592 ; 5169,3847 v1(5329.5,3847)
  L03 - SIG w6: 4914,3592 5169,3847
  L08 - BOTTOM w8: U29.8@4569.14,2778.24 4619.03,2778.24 v1(4619.18,2778.39)
PWM_C6_H: MD1.L3 R211.1 U30.7 | length 2652.6
  L01 - TOP w6: v1(5397,4316.5) 5397.33,4316.5 5430.77,4283.06 MD1.L3@5431.1,4283.06
  L01 - TOP w8: v1(4619.24,2401.84) 4621.47,2399.6 4638.4,2399.6 4658.56,2379.44 R211.1@4683.42,2379.44
  L08 - BOTTOM w4.25: v1(4619.24,2401.84) 4732.36,2401.84 4739.72,2409.19 4797.11,2409.19 4842.39,2454.47 4842.39,2641.39 5039.5,2838.5 5039.5,4205 5094.5,4260 5277.92,4260 5311.47,4293.55 5374.05,4293.55 v1(5397,4316.5)
  L08 - BOTTOM w8: U30.7@4568.94,2401.9 4619.18,2401.9 v1(4619.24,2401.84)
PWM_C6_L: MD1.L4 R212.1 U30.8 | length 2736.4
  L01 - TOP w6: v1(5455.5,4317.5) 5470.06,4302.94 5476.11,4302.94 5495.98,4283.06 MD1.L4@5498.03,4283.06
  L01 - TOP w8: v1(4619.18,2376.9) 4621.42,2374.66 4632.34,2374.66 4646,2361 4646,2350.19 4650.69,2345.5 4651.44,2345.5 4658.01,2338.93 4676.23,2338.93 R212.1@4683.6,2331.56
  L08 - BOTTOM w4.25: v1(4619.18,2376.9) 4620.65,2375.42 4719.03,2375.42 4743.55,2399.94 4800.94,2399.94 4851.64,2450.64 4851.64,2635.64 5051.57,2835.57 5051.57,4184.57 5111,4244 5302.72,4244 5343.02,4284.3 5422.3,4284.3 v1(5455.5,4317.5)
  L08 - BOTTOM w8: U30.8@4569.14,2376.75 4619.03,2376.75 v1(4619.18,2376.9)
PWMA1H: C72.1 J11.12 R133.2 | length 5025.3
  L01 - TOP w8: v1@4130.75,5149.75 v1(4131,5149.5) v1@4131.89,5150.39
  L06 - SIG w5.25: J11.12@1570,7549.2 1569,7550.2 1569,7628.1 1650,7709.1 3627.9,7709.1 3743.23,7593.77 3743.23,5633.27 4130.5,5246 4130.5,5150 v1(4131,5149.5)
  L08 - BOTTOM w8: C72.1@4088.61,5151.32 4089.52,5150.41 4130.09,5150.41 v1(4131,5149.5) R133.2@4171.75,5149.52
PWMA1L: C71.1 J11.14 R135.2 | length 4950.4
  L01 - TOP w8: v1@4130.25,5101.75 v1(4130.5,5102) v1@4130.89,5102.39
  L06 - SIG w5.25: J11.14@1670,7549.2 1666.5,7552.7 1666.5,7624.1 1740.5,7698.1 3616.4,7698.1 3727.79,7586.71 3727.79,5617.71 4104,5241.5 4104,5128.5 v1(4130.5,5102)
  L08 - BOTTOM w8: C71.1@4088.61,5102.82 4089.02,5102.41 4130.09,5102.41 v1(4130.5,5102) v1(4130.5,5102) 4171.72,5101.95 R135.2@4171.77,5101.9
PWMA2H: C86.1 J11.44 R161.2 | length 3455.4
  L06 - SIG w5.25: J11.44@3170,7549.2 3118.91,7498.11 3118.91,5540.59 3886,4773.5 4098.5,4773.5 v1(4127.7,4744.3)
  L08 - BOTTOM w8: C86.1@4083.12,4748.5 4085.22,4746.4 4125.6,4746.4 v1(4127.7,4744.3) R161.2@4168.44,4744.31
PWMA2L: C85.1 J11.42 R163.2 | length 3532.8
  L06 - SIG w5.25: J11.42@3070,7549.2 3018.36,7497.56 3018.36,5613.14 3904.65,4726.85 4097.15,4726.85 v1(4127.2,4696.8)
  L08 - BOTTOM w8: C85.1@4083.12,4701 4085.22,4698.9 4125.1,4698.9 v1(4127.2,4696.8) ; v1(4127.2,4696.8) R163.2@4168.41,4696.76
PWMA3H: C78.1 J12.12 R134.2 | length 3008.4
  L06 - SIG w5.25: J12.12@1570,4299.6 1569,4300.6 1569,4378.5 1650,4459.5 3729.5,4459.5 4086.36,4102.64 4086.36,3998.77 4101.05,3984.08 v1(4122.69,3984.08)
  L08 - BOTTOM w8: C78.1@4080.21,3986.18 4120.59,3986.18 v1(4122.69,3984.08) R134.2@4163.43,3984.08
PWMA3L: C77.1 J12.14 R136.2 | length 2943.4
  L06 - SIG w5.25: J12.14@1670,4299.6 1666.5,4303.1 1666.5,4374.5 1740.5,4448.5 3718,4448.5 4070.92,4095.58 4070.92,3951.02 4085.36,3936.58 v1(4122.19,3936.58)
  L08 - BOTTOM w8: C77.1@4080.21,3938.68 4120.09,3938.68 v1(4122.19,3936.58) ; v1@4122.24,3936.53 R136.2@4163.41,3936.53
PWMA4H: C92.1 J12.44 R162.2 | length 1998.8
  L06 - SIG w5.25: J12.44@3170,4299.6 3118.91,4248.51 3118.91,3514.09 3171.5,3461.5 4007.79,3461.5 4029.2,3482.9 4029.2,3536.45 4072.25,3579.5 v1(4128.5,3579.5)
  L08 - BOTTOM w8: C92.1@4088.91,3579.09 4089.12,3579.29 4128.29,3579.29 v1(4128.5,3579.5) 4129,3579 4168.38,3579 R162.2@4168.88,3578.5
PWMA4L: C91.1 J12.42 R164.2 | length 2126
  L06 - SIG w5.25: J12.42@3070,4299.6 3018.36,4247.96 3018.36,3500.64 3103,3416 4028.5,3416 4065,3452.5 4065,3505.65 4090.85,3531.5 v1(4129.5,3531.5)
  L08 - BOTTOM w8: C91.1@4088.62,3531.5 v1(4129.5,3531.5) 4129.75,3531.25 4168.63,3531.25 R164.2@4168.88,3531
PWMA5H: C100.1 J13.12 R187.2 | length 3811
  L06 - SIG w5.25: J13.12@1570,1050 1570,1733 2732.5,2895.5 4103,2895.5 v1(4127,2919.5)
  L08 - BOTTOM w8: C100.1@4087.62,2919.29 4126.79,2919.29 v1(4127,2919.5) 4127.5,2919 R187.2@4166.88,2919
PWMA5L: C99.1 J13.14 R188.2 | length 3722
  L06 - SIG w5.25: J13.14@1670,1050 1670,1783 2737,2850 4106.5,2850 v1(4128,2871.5)
  L08 - BOTTOM w8: C99.1@4087.12,2871.5 C99.1@4087.62,2871.5 v1(4128,2871.5) 4128.25,2871.25 R188.2@4167.13,2871.25
PWMA6H: C107.1 J13.44 R201.2 | length 2237.7
  L06 - SIG w5.25: J13.44@3170,1050 3168.5,1051.5 3168.5,1121.5 3228,1181 3446,1181 3714,1449 3714,1880.5 4062,2228.5 4142,2228.5 4175.32,2261.82 4175.32,2341.4 4159.17,2357.55 4116.25,2357.55 4108.03,2365.76 4108.03,2444.75 4113.79,2450.5 4137.2,2450.5 4143.47,2456.77 4143.47,2513.46 4138.42,2518.5 v1(4125,2518.5)
  L08 - BOTTOM w8: C107.1@4085.12,2518.29 4124.79,2518.29 v1(4125,2518.5) 4125.5,2518 R201.2@4164.88,2518
PWMA6L: C106.1 J13.42 R202.2 | length 2236.9
  L06 - SIG w5.25: J13.42@3070,1050 3070,1104.69 3158.81,1193.5 3440.5,1193.5 3702,1455 3702,1888.5 4057,2243.5 4137.5,2243.5 4161.2,2267.2 4161.2,2335.79 4149.7,2347.3 4112,2347.3 4097.68,2361.62 4097.68,2462.62 4105.56,2470.5 v1(4126,2470.5)
  L08 - BOTTOM w8: C106.1@4085.12,2470.5 v1(4126,2470.5) 4126.25,2470.25 R202.2@4165.13,2470.25
PWMB1H: C70.1 J11.16 R137.2 | length 4882.9
  L01 - TOP w8: v1@4129,5053.5 v1(4130,5054.5)
  L06 - SIG w5.25: J11.16@1770,7549.2 1769.5,7549.7 1769.5,7626.6 1829.5,7686.6 3601.4,7686.6 3714.37,7573.63 3714.37,5595.63 4078.5,5231.5 4078.5,5082.95 4106.95,5054.5 v1(4130,5054.5)
  L08 - BOTTOM w8: C70.1@4089.12,5054.5 v1(4130,5054.5) 4130.25,5054.25 4171.25,5054.25 R137.2@4171.5,5054
PWMB1L: C69.1 J11.18 R139.2 | length 4818.3
  L01 - TOP w8: v1@4128,5006.5 v1(4130,5008.5) v1@4131.1,5007.4
  L06 - SIG w5.25: J11.18@1870,7549.2 1870,7632.1 1912.5,7674.6 3589.4,7674.6 3700.76,7563.24 3700.76,5575.74 4054.97,5221.53 4054.97,5050.92 4098.47,5007.41 4128.91,5007.41 v1(4130,5008.5)
  L08 - BOTTOM w8: C69.1@4088.66,5006.33 4089.75,5007.41 4128.91,5007.41 v1(4130,5008.5) R139.2@4171.69,5008.54
PWMB2H: C84.1 J11.48 R165.2 | length 3540.6
  L06 - SIG w5.25: J11.48@3370,7549.2 3319,7498.2 3319,5393 3907.5,4804.5 4135.37,4804.5 4184.08,4755.79 4184.08,4676.85 4156.29,4649.05 4126.95,4649.05 v1(4126.7,4649.3)
  L08 - BOTTOM w8: C84.1@4083.12,4653.5 4085.22,4651.4 4124.6,4651.4 v1(4126.7,4649.3) ; v1@4126.95,4649.05 R165.2@4167.95,4649.05
PWMB2L: C83.1 J11.46 R167.2 | length 3666
  L06 - SIG w5.25: J11.46@3270,7549.2 3218,7497.2 3218,5470.5 3897.5,4791 4125.5,4791 4170.98,4745.52 4170.98,4685.71 4155.51,4670.23 4108.81,4670.23 4094.39,4655.81 4094.39,4615.41 4106.49,4603.3 v1(4126.7,4603.3)
  L08 - BOTTOM w8: C83.1@4083.12,4605 4083.97,4604.15 4125.85,4604.15 v1(4126.7,4603.3) R167.2@4168.36,4603.32
PWMB3H: C76.1 J12.16 R138.2 | length 2868.7
  L06 - SIG w5.25: J12.16@1770,4299.6 1769.5,4300.1 1769.5,4377 1829.5,4437 3703,4437 4057.5,4082.5 4057.5,3905.44 4073.87,3889.08 v1(4121.69,3889.08)
  L08 - BOTTOM w8: C76.1@4080.21,3891.18 4119.59,3891.18 v1(4121.69,3889.08) ; v1@4121.94,3888.83 R138.2@4162.94,3888.83
PWMB3L: C75.1 J12.18 R140.2 | length 2801.8
  L06 - SIG w5.25: J12.18@1870,4299.6 1870,4382.5 1912.5,4425 3691,4425 4043.89,4072.11 4043.89,3860.63 4061.45,3843.08 v1(4121.69,3843.08)
  L08 - BOTTOM w8: C75.1@4078.96,3843.93 4120.84,3843.93 v1(4121.69,3843.08) R140.2@4163.36,3843.1
PWMB4H: C90.1 J12.48 R166.2 | length 1950.1
  L06 - SIG w5.25: J12.48@3370,4299.6 3319,4248.6 3319,3580.5 3389.5,3510 3909,3510 3922.5,3523.5 3922.5,3600 3956.5,3634 4126,3634 4171.45,3588.55 4171.45,3509.35 4146.72,3484.62 4130.62,3484.62 v1(4129,3483)
  L08 - BOTTOM w8: C90.1@4088.62,3484 4089.12,3483.5 4128.5,3483.5 v1(4129,3483) R166.2@4168.88,3483
PWMB4L: C89.1 J12.46 R168.2 | length 2173.5
  L06 - SIG w5.25: J12.46@3270,4299.6 3218,4247.6 3218,3532.5 3269.5,3481 3924.5,3481 3941.5,3498 3941.5,3597.5 3962,3618 4122.5,3618 4156.8,3583.7 4156.8,3519.19 4142.11,3504.5 4111.82,3504.5 4097.42,3490.1 4097.42,3448.31 4110.23,3435.5 v1(4129,3435.5)
  L08 - BOTTOM w8: C89.1@4088.62,3436.5 4089.12,3436 4128.5,3436 v1(4129,3435.5) 4129.25,3435.25 4168.63,3435.25 R168.2@4168.88,3435
PWMB5H: C98.1 J13.16 R189.2 | length 3628.8
  L06 - SIG w5.25: J13.16@1770,1050 1770,1830 2740,2800 4104.5,2800 v1(4127.5,2823)
  L08 - BOTTOM w8: C98.1@4087.62,2823.5 4127,2823.5 v1(4127.5,2823) R189.2@4167.38,2823
PWMB5L: C97.1 J13.18 R190.2 | length 3533.3
  L06 - SIG w5.25: J13.18@1870,1050 1870,1871.5 2751,2752.5 4104.5,2752.5 v1(4127.5,2775.5)
  L08 - BOTTOM w8: C97.1@4087.62,2776 4127,2776 v1(4127.5,2775.5) 4127.75,2775.25 R190.2@4167.13,2775.25
PWMB6H: C105.1 J13.48 R203.2 | length 1966.4
  L06 - SIG w5.25: J13.48@3370,1050 3370,1113 3417.5,1160.5 3464,1160.5 3741.5,1438 3741.5,1870 4064,2192.5 4160,2192.5 4219.86,2252.36 4219.86,2394.55 4192.41,2422 v1(4125.5,2422)
  L08 - BOTTOM w8: C105.1@4084.94,2422.5 4125,2422.5 v1(4125.5,2422) R203.2@4165.38,2422
PWMB6L: C104.1 J13.46 R204.2 | length 1976.4
  L06 - SIG w5.25: J13.46@3270,1050 3270,1126.5 3314.25,1170.75 3454.75,1170.75 3728.5,1444.5 3728.5,1876 4064,2211.5 4150.84,2211.5 4196.19,2256.85 4196.19,2347.63 4168.8,2375.01 v1(4127.64,2375.01)
  L08 - BOTTOM w8: C104.1@4085.15,2374.65 4085.32,2374.82 4127.45,2374.82 v1(4127.64,2375.01) ; v1@4125.75,2374.25 R204.2@4165.13,2374.25
PWMC1H: C68.1 J11.20 R141.2 | length 4738.7
  L01 - TOP w8: v1@4126.76,4961.26 v1(4129,4963.5) v1@4131.24,4961.26
  L06 - SIG w5.25: J11.20@1970,7549.2 1970,7634.04 1998.56,7662.6 3577.9,7662.6 3687.42,7553.08 3687.42,5550.58 4032.98,5205.02 4032.98,5035.64 4104.26,4964.36 4128.14,4964.36 v1(4129,4963.5)
  L08 - BOTTOM w8: C68.1@4088.51,4957.08 4092.69,4961.26 4126.76,4961.26 v1(4129,4963.5) 4129.57,4962.93 4171.29,4962.93 R141.2@4171.87,4962.35
PWMC1L: C67.1 J11.22 R143.2 | length 4656.5
  L01 - TOP w8: v1@4127.26,4913.26 v1(4129.5,4915.5) v1@4131.67,4913.33
  L06 - SIG w5.25: J11.22@2070,7549.2 2070,7623.1 2097.5,7650.6 3569.4,7650.6 3673.5,7546.5 3673.5,5530 4015.78,5187.72 4015.78,5006.43 4106.7,4915.5 v1(4129.5,4915.5)
  L08 - BOTTOM w8: C67.1@4088.21,4911.19 4090.36,4913.35 4127.35,4913.35 v1(4129.5,4915.5) 4129.8,4915.2 4171.02,4915.2 R143.2@4171.32,4914.89
PWMC2H: C82.1 J11.40 R169.2 | length 3689.4
  L06 - SIG w5.25: J11.40@2970,7549.2 2920,7499.2 2920,5603.5 3942.5,4581 4103,4581 v1(4125.7,4558.3)
  L08 - BOTTOM w8: C82.1@4083.62,4557 4084.27,4557.65 4125.04,4557.65 v1(4125.7,4558.3) ; v1@4126.27,4557.73 R169.2@4167.99,4557.73
PWMC2L: C81.1 J11.38 R171.2 | length 3766.7
  L06 - SIG w5.25: J11.38@2870,7549.2 2821,7500.2 2821,5673 3959.5,4534.5 4102,4534.5 v1(4126.2,4510.3)
  L08 - BOTTOM w8: C81.1@4084.12,4510 4084.27,4510.15 4126.04,4510.15 v1(4126.2,4510.3) ; v1@4126.5,4510 R171.2@4167.71,4510
PWMC3H: C74.1 J12.20 R142.2 | length 2724.6
  L06 - SIG w5.25: J12.20@1970,4299.6 1970,4384.44 1998.56,4413 3679.5,4413 4030.55,4061.95 4030.55,3824.5 4056.97,3798.08 v1(4120.69,3798.08)
  L08 - BOTTOM w8: C74.1@4079.27,3797.43 4120.04,3797.43 v1(4120.69,3798.08) ; v1@4121.26,3797.5 R142.2@4162.99,3797.5
PWMC3L: C73.1 J12.22 R144.2 | length 2644.9
  L06 - SIG w5.25: J12.22@2070,4299.6 2070,4373.5 2097.5,4401 3671,4401 4016.63,4055.37 4016.63,3789.69 4056.24,3750.08 v1(4121.19,3750.08)
  L08 - BOTTOM w8: C73.1@4079.27,3749.93 4121.04,3749.93 v1(4121.19,3750.08) ; v1@4121.49,3749.77 R144.2@4162.71,3749.77
PWMC4H: C88.1 J12.40 R170.2 | length 2164.1
  L06 - SIG w5.25: J12.40@2970,4299.6 2920,4249.6 2920,3518.5 3072.5,3366 4107.5,3366 v1(4129,3387.5)
  L08 - BOTTOM w8: C88.1@4088.12,3388.5 4088.62,3388 4128.5,3388 v1(4129,3387.5) R170.2@4168.88,3387.5
PWMC4L: C87.1 J12.38 R172.2 | length 2283
  L06 - SIG w5.25: J12.38@2870,4299.6 2821,4250.6 2821,3535 3051,3305 4093.5,3305 v1(4129,3340.5)
  L08 - BOTTOM w8: C87.1@4088.62,3340.5 v1(4129,3340.5) 4129.5,3340 4167.88,3340 R172.2@4168.38,3339.5
PWMC5H: C96.1 J13.20 R191.2 | length 3444.8
  L06 - SIG w5.25: J13.20@1970,1050 1971.5,1051.5 1971.5,1925.5 2750,2704 4104,2704 v1(4127.5,2727.5)
  L08 - BOTTOM w8: C96.1@4087.12,2728 4127,2728 v1(4127.5,2727.5) R191.2@4167.38,2727.5
PWMC5L: C95.1 J13.22 R192.2 | length 3350.1
  L06 - SIG w5.25: J13.22@2070,1050 2070,1968 2759,2657 4104,2657 v1(4127.5,2680.5)
  L08 - BOTTOM w8: C95.1@4087.12,2680.5 v1(4127.5,2680.5) 4128,2680 R192.2@4166.38,2680
PWMC6H: C103.1 J13.40 R205.2 | length 2130.5
  L06 - SIG w5.25: J13.40@2970,1050 2970,1118 3063.5,1211.5 3440.5,1211.5 3691,1462 3691,1897.5 4050.35,2256.85 4136.35,2256.85 4145.19,2265.68 4145.19,2319.24 4137.92,2326.5 v1(4125.5,2326.5)
  L08 - BOTTOM w8: C103.1@4085.01,2327 4125,2327 v1(4125.5,2326.5) R205.2@4165.38,2326.5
